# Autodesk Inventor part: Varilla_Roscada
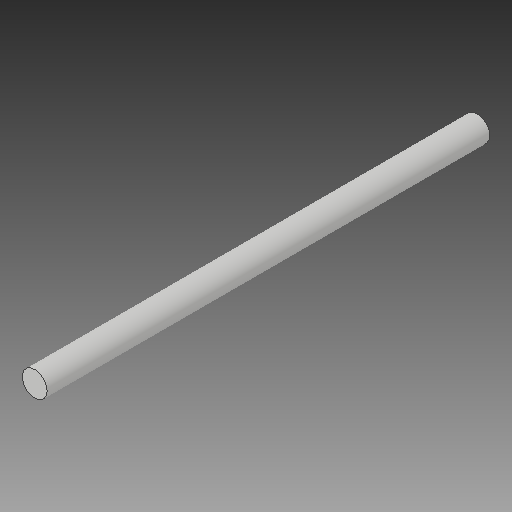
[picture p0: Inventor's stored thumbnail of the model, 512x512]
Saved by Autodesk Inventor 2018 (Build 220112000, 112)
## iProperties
Part Number: Varilla_Roscada
Material: Genérico
Document SubType Name: Modeling
Designer: ULISES
Density: 1 g/cm^3
Appearance: Valor por defecto
Author: ULISES
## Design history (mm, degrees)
sketch "Boceto1"
  geometry: C1 r 4 at (0, 0); 1 further point
  constraints: 1 centre point, 1 coincident
  dimensions: "d0" = 8 diameter of C1
extrude "Extrusión1" new body sketch "Boceto1" distance "d1" = 142; taper "d2" = 0 deg
node "Sólido1"
